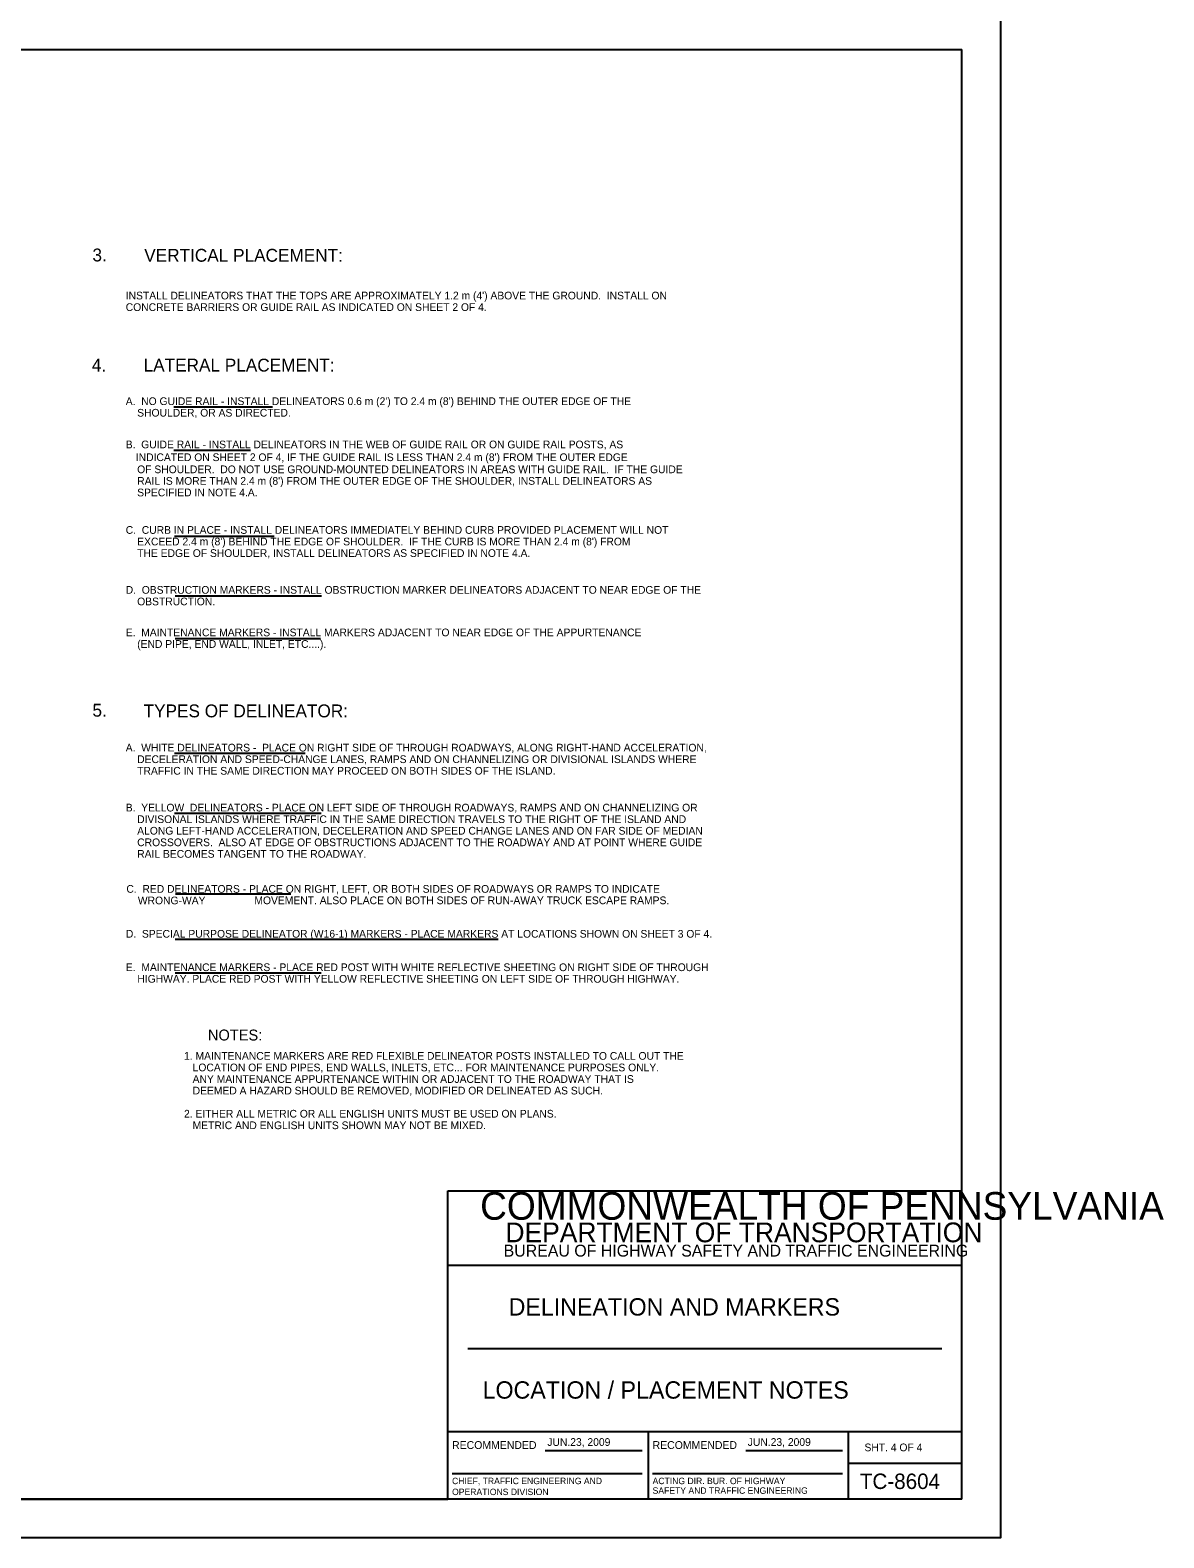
# Model space of a CAD drawing. Extents: x 640253 to 641999, y 298458 to 299646.
# Drawn here: x 641558 to 641999, y 298458 to 299044 of the extents above; entities that cross this region are included whole.
import ezdxf

# ---------------------------------------------------------------- set-up
doc = ezdxf.new("R2010")
doc.units = 0
for name, color, linetype in [('1', 7, 'Continuous'), ('2', 7, 'Continuous'), ('PLT-BNDY', 7, 'Continuous')]:
    doc.layers.add(name, color=color, linetype=linetype)

msp = doc.modelspace()

# ---------------------------------------------------------------- linework, layer by layer
at = {"layer": '1'}
for p, q in [((641134.31, 299036.63), (641920.31, 299036.63)), ((641920.31, 298472.63), (641920.31, 299036.63)), ((641720.31, 298472.63), (641720.31, 298592.63)), ((641720.31, 298592.63), (641920.31, 298592.63)), ((641920.31, 298563.63), (641720.31, 298563.63)), ((641728.06, 298531.31), (641912.56, 298531.31)), ((641720.31, 298499), (641920.31, 298499)), ((641798.31, 298499), (641798.31, 298472.63)), ((641876.19, 298472.63), (641876.19, 298499)), ((641758.24, 298491.57), (641795.87, 298491.57)), ((641836.24, 298491.57), (641873.87, 298491.57)), ((641721.99, 298482.68), (641795.87, 298482.68)), ((641799.99, 298482.68), (641873.87, 298482.68)), ((641876.19, 298486.63), (641920.31, 298486.63)), ((641920.31, 298472.63), (641134.31, 298472.63)), ((641134.31, 298472.63), (641720.31, 298472.63))]:
    msp.add_line(p, q, dxfattribs=at)
at = {"layer": '2'}
for p, q in [((641613.73, 298897.59), (641652.08, 298897.59)), ((641613.73, 298880.68), (641643.54, 298880.68)), ((641613.99, 298847.24), (641652.76, 298847.24)), ((641614.25, 298824.09), (641671.21, 298824.09)), ((641614.25, 298807.53), (641670.78, 298807.53)), ((641613.99, 298762.89), (641664.87, 298762.89)), ((641613.99, 298739.54), (641671.05, 298739.54)), ((641614.46, 298708.18), (641659.32, 298708.18)), ((641614.33, 298690.48), (641739.94, 298690.48)), ((641614.33, 298677.47), (641671.03, 298677.47))]:
    msp.add_line(p, q, dxfattribs=at)
at = {"layer": 'PLT-BNDY'}
msp.add_lwpolyline([(641094.31, 299051.63), (641935.31, 299051.63), (641935.31, 298457.63), (641094.31, 298457.63)], close=True, dxfattribs=at)

# ---------------------------------------------------------------- texts
at = {"layer": '1'}
for s, height, p in [('COMMONWEALTH OF PENNSYLVANIA', 10.7828, (641732.9, 298581.36)), ('DEPARTMENT OF TRANSPORTATION', 7.6837, (641742.76, 298572.61)), ('BUREAU OF HIGHWAY SAFETY AND TRAFFIC ENGINEERING', 4.6253, (641742.04, 298567.04)), ('DELINEATION AND MARKERS', 6.75, (641743.99, 298544.1)), ('LOCATION / PLACEMENT NOTES', 6.75, (641733.86, 298511.78)), ('RECOMMENDED', 3.048, (641721.99, 298492.2)), ('JUN.23, 2009', 3, (641759.03, 298493.4)), ('RECOMMENDED', 3.048, (641799.99, 298492.2)), ('JUN.23, 2009', 3, (641837, 298493.4)), ('SHT. 4 OF 4', 3, (641882.4, 298491.31)), ('TC-8604', 6, (641880.6, 298476.63)), ('OPERATIONS DIVISION', 2.5, (641721.99, 298474.26)), ('CHIEF, TRAFFIC ENGINEERING AND', 2.5, (641721.99, 298478.51)), ('ACTING DIR. BUR. OF HIGHWAY', 2.5, (641799.99, 298478.51)), ('SAFETY AND TRAFFIC ENGINEERING', 2.5, (641799.99, 298474.76))]:
    msp.add_text(s, height=height, dxfattribs=at).set_placement(p)
at = {"layer": '2'}
for s, height, p in [('3.', 5, (641582.09, 298954.17)), ('VERTICAL PLACEMENT:', 5, (641602.24, 298954.04)), ("    INSTALL DELINEATORS THAT THE TOPS ARE APPROXIMATELY 1.2 m (4') ABOVE THE GROUND.  INSTALL ON ", 3, (641590.58, 298939.38)), ('    CONCRETE BARRIERS OR GUIDE RAIL AS INDICATED ON SHEET 2 OF 4.', 3, (641590.58, 298934.88)), ('4.', 5, (641581.84, 298911.32)), ('LATERAL PLACEMENT:', 5, (641601.99, 298911.32)), ("    A.  NO GUIDE RAIL - INSTALL DELINEATORS 0.6 m (2') TO 2.4 m (8') BEHIND THE OUTER EDGE OF THE ", 3, (641590.58, 298898.29)), ('        SHOULDER, OR AS DIRECTED.', 3, (641590.58, 298893.79)), ('    B.  GUIDE RAIL - INSTALL DELINEATORS IN THE WEB OF GUIDE RAIL OR ON GUIDE RAIL POSTS, AS', 3, (641590.58, 298881.46)), ("        INDICATED ON SHEET 2 OF 4, IF THE GUIDE RAIL IS LESS THAN 2.4 m (8') FROM THE OUTER EDGE", 3, (641590.05, 298876.49)), ('        OF SHOULDER.  DO NOT USE GROUND-MOUNTED DELINEATORS IN AREAS WITH GUIDE RAIL.  IF THE GUIDE', 3, (641590.58, 298871.78)), ("        RAIL IS MORE THAN 2.4 m (8') FROM THE OUTER EDGE OF THE SHOULDER, INSTALL DELINEATORS AS", 3, (641590.58, 298867.28)), ('        SPECIFIED IN NOTE 4.A. ', 3, (641590.58, 298862.78)), ('    C.  CURB IN PLACE - INSTALL DELINEATORS IMMEDIATELY BEHIND CURB PROVIDED PLACEMENT WILL NOT', 3, (641590.58, 298848.2)), ("        EXCEED 2.4 m (8') BEHIND THE EDGE OF SHOULDER.  IF THE CURB IS MORE THAN 2.4 m (8') FROM ", 3, (641590.58, 298843.7)), ('        THE EDGE OF SHOULDER, INSTALL DELINEATORS AS SPECIFIED IN NOTE 4.A.    ', 3, (641590.58, 298839.2)), ('    D.  OBSTRUCTION MARKERS - INSTALL OBSTRUCTION MARKER DELINEATORS ADJACENT TO NEAR EDGE OF THE', 3, (641590.58, 298824.89)), ('        OBSTRUCTION.', 3, (641590.58, 298820.39)), ('    E.  MAINTENANCE MARKERS - INSTALL MARKERS ADJACENT TO NEAR EDGE OF THE APPURTENANCE', 3, (641590.58, 298808.34)), ('        (END PIPE, END WALL, INLET, ETC....).', 3, (641590.58, 298803.84)), ('5.', 5, (641582.09, 298777.07)), ('TYPES OF DELINEATOR:', 5, (641601.99, 298776.81)), ('    A.  WHITE DELINEATORS -  PLACE ON RIGHT SIDE OF THROUGH ROADWAYS, ALONG RIGHT-HAND ACCELERATION,', 3, (641590.58, 298763.52)), ('        TRAFFIC IN THE SAME DIRECTION MAY PROCEED ON BOTH SIDES OF THE ISLAND.', 3, (641590.58, 298754.52)), ('        DECELERATION AND SPEED-CHANGE LANES, RAMPS AND ON CHANNELIZING OR DIVISIONAL ISLANDS WHERE', 3, (641590.58, 298759.02)), ('    B.  YELLOW  DELINEATORS - PLACE ON LEFT SIDE OF THROUGH ROADWAYS, RAMPS AND ON CHANNELIZING OR', 3, (641590.58, 298740.19)), ('        ALONG LEFT-HAND ACCELERATION, DECELERATION AND SPEED CHANGE LANES AND ON FAR SIDE OF MEDIAN', 3, (641590.58, 298731.19)), ('        DIVISONAL ISLANDS WHERE TRAFFIC IN THE SAME DIRECTION TRAVELS TO THE RIGHT OF THE ISLAND AND', 3, (641590.58, 298735.69)), ('        CROSSOVERS.  ALSO AT EDGE OF OBSTRUCTIONS ADJACENT TO THE ROADWAY AND AT POINT WHERE GUIDE', 3, (641590.58, 298726.69)), ('        RAIL BECOMES TANGENT TO THE ROADWAY.', 3, (641590.58, 298722.19)), ('    C.  RED DELINEATORS - PLACE ON RIGHT, LEFT, OR BOTH SIDES OF ROADWAYS OR RAMPS TO INDICATE', 3, (641590.84, 298708.57)), ('        WRONG-WAY ', 3, (641590.84, 298704.07)), ('MOVEMENT. ALSO PLACE ON BOTH SIDES OF RUN-AWAY TRUCK ESCAPE RAMPS.', 3, (641645.09, 298704.12)), ('    D.  SPECIAL PURPOSE DELINEATOR (W16-1) MARKERS - PLACE MARKERS AT LOCATIONS SHOWN ON SHEET 3 OF 4.', 3, (641590.64, 298691.1)), ('    E.  MAINTENANCE MARKERS - PLACE RED POST WITH WHITE REFLECTIVE SHEETING ON RIGHT SIDE OF THROUGH', 3, (641590.64, 298678.09)), ('        HIGHWAY. PLACE RED POST WITH YELLOW REFLECTIVE SHEETING ON LEFT SIDE OF THROUGH HIGHWAY.', 3, (641590.64, 298673.59)), ('NOTES:', 4.25, (641627, 298651.1)), ('1. MAINTENANCE MARKERS ARE RED FLEXIBLE DELINEATOR POSTS INSTALLED TO CALL OUT THE', 3, (641617.72, 298643.61)), ('   LOCATION OF END PIPES, END WALLS, INLETS, ETC... FOR MAINTENANCE PURPOSES ONLY.', 3, (641617.72, 298639.11)), ('   ANY MAINTENANCE APPURTENANCE WITHIN OR ADJACENT TO THE ROADWAY THAT IS', 3, (641617.72, 298634.61)), ('   DEEMED A HAZARD SHOULD BE REMOVED, MODIFIED OR DELINEATED AS SUCH.', 3, (641617.72, 298630.11)), ('2. EITHER ALL METRIC OR ALL ENGLISH UNITS MUST BE USED ON PLANS.  ', 3, (641617.72, 298621.11)), ('   METRIC AND ENGLISH UNITS SHOWN MAY NOT BE MIXED.', 3, (641617.72, 298616.61))]:
    msp.add_text(s, height=height, dxfattribs=at).set_placement(p)

doc.saveas('drawing.dxf')
